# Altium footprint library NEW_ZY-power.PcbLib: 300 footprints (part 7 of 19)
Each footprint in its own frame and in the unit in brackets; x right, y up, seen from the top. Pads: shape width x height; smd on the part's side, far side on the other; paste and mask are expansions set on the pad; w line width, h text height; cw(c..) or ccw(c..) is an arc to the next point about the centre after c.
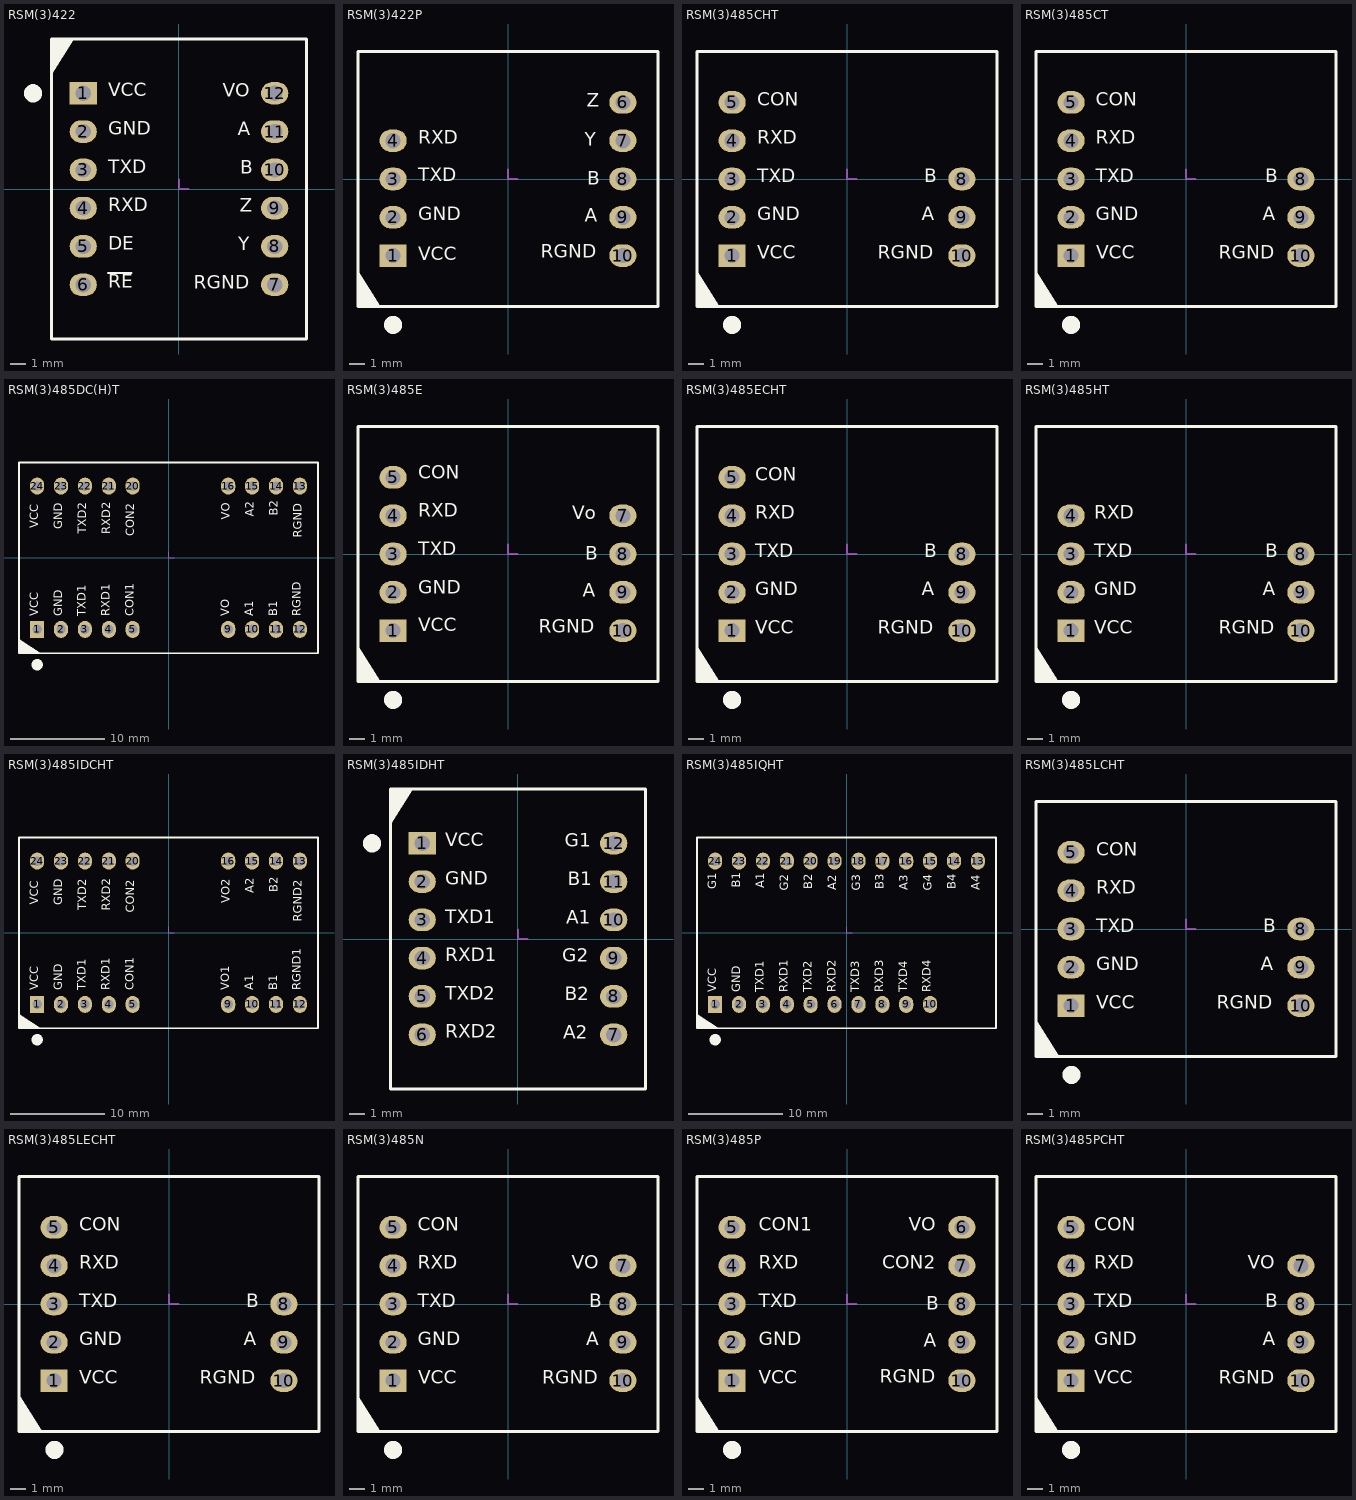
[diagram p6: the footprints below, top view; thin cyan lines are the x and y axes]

## RSM(3)422 [mm]
height 7.05
pads (12):
  rect 1.8x1.5 hole 1: 1(-6.35,6.35)
  oval 1.8x1.5 hole 1: 2(-6.35,3.81) 3(-6.35,1.27) 4(-6.35,-1.27) 5(-6.35,-3.81) 6(-6.35,-6.35) 7(6.35,-6.35) 8(6.35,-3.81) 9(6.35,-1.27) 10(6.35,1.27) 11(6.35,3.81) 12(6.35,6.35)
Top Overlay:
  circle w1: c-9.675,6.35 r0.1
  region: -8.45,7.62 -8.45,9.95 -6.99,9.95
  lines w0.152: -4.694,-5.575 -3.144,-5.575
  lines w0.2: -8.45,-9.95 -8.45,9.95 8.45,9.95 8.45,-9.95 -8.45,-9.95
  text "DE" at -4.7,-4.318 h1.52
  text "RE" at -4.7,-6.858 h1.52
  text "RGND" at 0.983,-6.909 h1.52
  text "Y" at 3.92,-4.364 h1.52
  text "RXD" at -4.7,-1.778 h1.52
  text "TXD" at -4.7,0.762 h1.52
  text "GND" at -4.7,3.302 h1.52
  text "VCC" at -4.699,5.842 h1.52
  text "A" at 3.903,3.272 h1.52
  text "B" at 4.076,0.726 h1.52
  text "Z" at 4.042,-1.819 h1.52
  text "VO" at 2.911,5.817 h1.52
Mechanical 15:
  lines w0.127: 0,0.635 0,0 0.635,0

## RSM(3)422P [mm]
height 7.05
pads (9):
  rect 1.8x1.5 hole 1: 1(-7.62,-5.08)
  oval 1.8x1.5 hole 1: 2(-7.62,-2.54) 3(-7.62,0) 4(-7.62,2.54) 6(7.62,5.08) 7(7.62,2.54) 8(7.62,0) 9(7.62,-2.54) 10(7.62,-5.08)
Top Overlay:
  circle w1: c-7.62,-9.675 r0.1
  region: -9.95,-6.12 -9.95,-8.45 -8.49,-8.45
  lines w0.2: -9.95,-8.45 -9.95,8.45 9.95,8.45 9.95,-8.45 -9.95,-8.45
  text "RGND" at 2.159,-5.537 h1.52
  text "A" at 5.079,-3.124 h1.52
  text "B" at 5.253,-0.686 h1.52
  text "Y" at 5.097,1.905 h1.52
  text "Z" at 5.218,4.496 h1.52
  text "RXD" at -5.969,2.032 h1.52
  text "TXD" at -5.969,-0.457 h1.52
  text "GND" at -5.969,-3.023 h1.52
  text "VCC" at -5.969,-5.69 h1.52
Mechanical 15:
  lines w0.127: 0,0.635 0,0 0.635,0

## RSM(3)485CHT [mm] "嵌入式隔离RS-485收发器"
height 7
pads (8):
  rect 1.8x1.5 hole 1: 1(-7.62,-5.08)
  oval 1.8x1.5 hole 1: 2(-7.62,-2.54) 3(-7.62,0) 4(-7.62,2.54) 5(-7.62,5.08) 8(7.62,0) 9(7.62,-2.54) 10(7.62,-5.08)
Top Overlay:
  circle w1: c-7.62,-9.675 r0.1
  region: -9.95,-6.12 -9.95,-8.45 -8.49,-8.45
  lines w0.2: -9.95,-8.45 9.95,-8.45 9.95,8.45 -9.95,8.45 -9.95,-8.45
  text "A" at 4.952,-3.048 h1.52
  text "B" at 5.126,-0.508 h1.52
  text "RGND" at 2.032,-5.588 h1.52
  text "TXD" at -5.969,-0.508 h1.52
  text "RXD" at -5.969,2.032 h1.52
  text "GND" at -5.969,-3.048 h1.52
  text "CON" at -5.969,4.572 h1.52
  text "VCC" at -5.969,-5.588 h1.52
Mechanical 15:
  lines w0.127: 0,0.635 0,0 0.635,0

## RSM(3)485CT [mm] "嵌入式隔离RS-485收发器"
height 7
pads (8):
  rect 1.8x1.5 hole 1: 1(-7.62,-5.08)
  oval 1.8x1.5 hole 1: 2(-7.62,-2.54) 3(-7.62,0) 4(-7.62,2.54) 5(-7.62,5.08) 8(7.62,0) 9(7.62,-2.54) 10(7.62,-5.08)
Top Overlay:
  circle w1: c-7.62,-9.675 r0.1
  region: -9.95,-6.12 -9.95,-8.45 -8.49,-8.45
  lines w0.2: -9.95,-8.45 9.95,-8.45 9.95,8.45 -9.95,8.45 -9.95,-8.45
  text "A" at 5.079,-3.048 h1.52
  text "B" at 5.253,-0.508 h1.52
  text "RGND" at 2.159,-5.588 h1.52
  text "TXD" at -5.97,-0.508 h1.52
  text "RXD" at -5.97,2.032 h1.52
  text "GND" at -5.97,-3.048 h1.52
  text "CON" at -5.97,4.572 h1.52
  text "VCC" at -5.969,-5.588 h1.52
Mechanical 15:
  lines w0.127: 0,0.635 0,0 0.635,0

## RSM(3)485DC(H)T [mm]
height 9.5
pads (18):
  rect 1.5x1.8 hole 1: 1(-13.97,-7.62)
  oval 1.5x1.8 hole 1: 2(-11.43,-7.62) 3(-8.89,-7.62) 4(-6.35,-7.62) 5(-3.81,-7.62) 9(6.35,-7.62) 10(8.89,-7.62) 11(11.43,-7.62) 12(13.97,-7.62) 13(13.97,7.62) 14(11.43,7.62) 15(8.89,7.62) 16(6.35,7.62) 20(-3.81,7.62) 21(-6.35,7.62) 22(-8.89,7.62) 23(-11.43,7.62) 24(-13.97,7.62)
Top Overlay:
  circle w1: c-13.97,-11.375 r0.1
  region: -13.57,-10.15 -15.9,-10.15 -15.9,-8.69
  lines w0.2: -15.9,-10.15 15.9,-10.15 15.9,10.15 -15.9,10.15 -15.9,-10.15
  text "VCC" at -13.538,-6.223 h1.52
  text "GND" at -10.998,-6.224 h1.52
  text "TXD1" at -8.458,-6.224 h1.52
  text "RXD1" at -5.918,-6.224 h1.52
  text "CON1" at -3.378,-6.224 h1.52
  text "VO" at 6.782,-6.223 h1.52
  text "A1" at 9.322,-6.224 h1.52
  text "B1" at 11.862,-6.224 h1.52
  text "RGND" at 14.402,-6.224 h1.52
  text "RGND" at 14.478,2.108 h1.52
  text "B2" at 11.931,4.443 h1.52
  text "A2" at 9.384,4.342 h1.52
  text "VO" at 6.837,4.037 h1.52
  text "VCC" at -13.538,3.122 h1.52
  text "GND" at -10.991,3.058 h1.52
  text "TXD2" at -8.444,2.56 h1.52
  text "CON2" at -3.35,2.294 h1.52
  text "RXD2" at -5.897,2.483 h1.52
Mechanical 15:
  lines w0.127: 0,0.635 0,0 0.635,0

## RSM(3)485E [mm]
height 7.05
pads (9):
  rect 1.8x1.5 hole 1: 1(-7.62,-5.08)
  oval 1.8x1.5 hole 1: 2(-7.62,-2.54) 3(-7.62,0) 4(-7.62,2.54) 5(-7.62,5.08) 7(7.62,2.54) 8(7.62,0) 9(7.62,-2.54) 10(7.62,-5.08)
Top Overlay:
  circle w1: c-7.62,-9.675 r0.1
  region: -9.95,-6.12 -9.95,-8.45 -8.49,-8.45
  lines w0.2: -9.95,-8.45 9.95,-8.45 9.95,8.45 -9.95,8.45 -9.95,-8.45
  text "VCC" at -5.969,-5.436 h1.52
  text "GND" at -5.969,-2.921 h1.52
  text "TXD" at -5.969,-0.381 h1.52
  text "RXD" at -5.969,2.159 h1.52
  text "CON" at -5.969,4.699 h1.52
  text "Vo" at 4.252,2.007 h1.52
  text "B" at 5.126,-0.686 h1.52
  text "A" at 4.952,-3.124 h1.52
  text "RGND" at 2.032,-5.537 h1.52
Mechanical 15:
  lines w0.127: 0,0.635 0,0 0.635,0

## RSM(3)485ECHT [mm]
height 7.05
pads (8):
  rect 1.8x1.5 hole 1: 1(-7.62,-5.08)
  oval 1.8x1.5 hole 1: 2(-7.62,-2.54) 3(-7.62,0) 4(-7.62,2.54) 5(-7.62,5.08) 8(7.62,0) 9(7.62,-2.54) 10(7.62,-5.08)
Top Overlay:
  circle w1: c-7.62,-9.675 r0.1
  region: -9.95,-6.12 -9.95,-8.45 -8.49,-8.45
  lines w0.2: -9.95,-8.45 9.95,-8.45 9.95,8.45 -9.95,8.45 -9.95,-8.45
  text "A" at 4.952,-3.048 h1.52
  text "B" at 5.126,-0.508 h1.52
  text "RGND" at 2.032,-5.588 h1.52
  text "TXD" at -6.097,-0.508 h1.52
  text "RXD" at -6.097,2.032 h1.52
  text "GND" at -6.097,-3.048 h1.52
  text "CON" at -6.097,4.572 h1.52
  text "VCC" at -6.096,-5.588 h1.52
Mechanical 15:
  lines w0.127: 0,0.635 0,0 0.635,0

## RSM(3)485HT [mm]
height 7.05
pads (7):
  rect 1.8x1.5 hole 1: 1(-7.62,-5.08)
  oval 1.8x1.5 hole 1: 2(-7.62,-2.54) 3(-7.62,0) 4(-7.62,2.54) 8(7.62,0) 9(7.62,-2.54) 10(7.62,-5.08)
Top Overlay:
  circle w1: c-7.62,-9.675 r0.1
  region: -9.95,-6.12 -9.95,-8.45 -8.49,-8.45
  lines w0.2: -9.95,-8.45 -9.95,8.45 9.95,8.45 9.95,-8.45 -9.95,-8.45
  text "VCC" at -6.096,-5.588 h1.52
  text "GND" at -6.097,-3.048 h1.52
  text "RXD" at -6.097,2.032 h1.52
  text "TXD" at -6.097,-0.508 h1.52
  text "RGND" at 2.159,-5.588 h1.52
  text "B" at 5.253,-0.508 h1.52
  text "A" at 5.079,-3.048 h1.52
Mechanical 15:
  lines w0.127: 0,0.635 0,0 0.635,0

## RSM(3)485IDCHT [mm]
height 6.5
pads (18):
  rect 1.5x1.8 hole 1: 1(-13.97,-7.62)
  oval 1.5x1.8 hole 1: 2(-11.43,-7.62) 3(-8.89,-7.62) 4(-6.35,-7.62) 5(-3.81,-7.62) 9(6.35,-7.62) 10(8.89,-7.62) 11(11.43,-7.62) 12(13.97,-7.62) 13(13.97,7.62) 14(11.43,7.62) 15(8.89,7.62) 16(6.35,7.62) 20(-3.81,7.62) 21(-6.35,7.62) 22(-8.89,7.62) 23(-11.43,7.62) 24(-13.97,7.62)
Top Overlay:
  circle w1: c-13.97,-11.375 r0.1
  region: -13.57,-10.15 -15.9,-10.15 -15.9,-8.69
  lines w0.2: -15.9,-10.15 -15.9,10.15 15.9,10.15 15.9,-10.15 -15.9,-10.15
  text "RXD2" at -5.897,2.328 h1.52
  text "CON2" at -3.35,2.139 h1.52
  text "TXD2" at -8.444,2.405 h1.52
  text "GND" at -10.991,2.903 h1.52
  text "VCC" at -13.538,2.966 h1.52
  text "VO2" at 6.837,3.134 h1.52
  text "A2" at 9.384,4.186 h1.52
  text "B2" at 11.931,4.287 h1.52
  text "RGND2" at 14.478,1.194 h1.52
  text "RGND1" at 14.402,-6.097 h1.52
  text "B1" at 11.862,-6.097 h1.52
  text "A1" at 9.322,-6.097 h1.52
  text "VO1" at 6.782,-6.096 h1.52
  text "CON1" at -3.378,-6.097 h1.52
  text "RXD1" at -5.918,-6.097 h1.52
  text "TXD1" at -8.458,-6.097 h1.52
  text "GND" at -10.998,-6.097 h1.52
  text "VCC" at -13.538,-6.096 h1.52
Mechanical 15:
  lines w0.127: 0,0.635 0,0 0.635,0

## RSM(3)485IDHT [mm]
height 7.05
pads (12):
  rect 1.8x1.5 hole 1: 1(-6.35,6.35)
  oval 1.8x1.5 hole 1: 2(-6.35,3.81) 3(-6.35,1.27) 4(-6.35,-1.27) 5(-6.35,-3.81) 6(-6.35,-6.35) 7(6.35,-6.35) 8(6.35,-3.81) 9(6.35,-1.27) 10(6.35,1.27) 11(6.35,3.81) 12(6.35,6.35)
Top Overlay:
  circle w1: c-9.675,6.35 r0.1
  region: -8.45,7.62 -8.45,9.95 -6.99,9.95
  lines w0.2: -8.45,-9.95 8.45,-9.95 8.45,9.95 -8.45,9.95 -8.45,-9.95
  text "G1" at 3.117,5.817 h1.52
  text "G2" at 2.939,-1.819 h1.52
  text "A1" at 3.193,0.726 h1.52
  text "B1" at 3.294,3.272 h1.52
  text "VCC" at -4.826,5.842 h1.52
  text "GND" at -4.827,3.302 h1.52
  text "TXD1" at -4.827,0.762 h1.52
  text "RXD1" at -4.827,-1.778 h1.52
  text "B2" at 3.115,-4.364 h1.52
  text "A2" at 3.014,-6.909 h1.52
  text "RXD2" at -4.827,-6.858 h1.52
  text "TXD2" at -4.827,-4.318 h1.52
Mechanical 15:
  lines w0.127: 0,0.635 0,0 0.635,0

## RSM(3)485IQHT [mm]
height 9.5
pads (22):
  rect 1.5x1.8 hole 1: 1(-13.97,-7.62)
  oval 1.5x1.8 hole 1: 2(-11.43,-7.62) 3(-8.89,-7.62) 4(-6.35,-7.62) 5(-3.81,-7.62) 6(-1.27,-7.62) 7(1.27,-7.62) 8(3.81,-7.62) 9(6.35,-7.62) 10(8.89,-7.62) 13(13.97,7.62) 14(11.43,7.62) 15(8.89,7.62) 16(6.35,7.62) 17(3.81,7.62) 18(1.27,7.62) 19(-1.27,7.62) 20(-3.81,7.62) 21(-6.35,7.62) 22(-8.89,7.62) 23(-11.43,7.62) 24(-13.97,7.62)
Top Overlay:
  circle w1: c-13.97,-11.375 r0.1
  region: -13.57,-10.15 -15.9,-10.15 -15.9,-8.69
  lines w0.2: -15.9,-10.15 -15.9,10.15 15.9,10.15 15.9,-10.15 -15.9,-10.15
  text "A2" at -0.79,4.53 h1.52
  text "G3" at 1.755,4.445 h1.52
  text "B3" at 4.3,4.622 h1.52
  text "RXD4" at 9.296,-6.326 h1.52
  text "TXD4" at 6.759,-6.326 h1.52
  text "RXD3" at 4.222,-6.326 h1.52
  text "TXD3" at 1.685,-6.326 h1.52
  text "RXD2" at -0.852,-6.326 h1.52
  text "G2" at -5.879,4.454 h1.52
  text "B2" at -3.334,4.631 h1.52
  text "A1" at -8.424,4.708 h1.52
  text "B1" at -10.968,4.809 h1.52
  text "G1" at -13.513,4.632 h1.52
  text "A3" at 6.844,4.521 h1.52
  text "G4" at 9.389,4.448 h1.52
  text "B4" at 11.933,4.625 h1.52
  text "A4" at 14.478,4.524 h1.52
  text "TXD2" at -3.389,-6.326 h1.52
  text "RXD1" at -5.927,-6.326 h1.52
  text "TXD1" at -8.464,-6.326 h1.52
  text "GND" at -11.001,-6.326 h1.52
  text "VCC" at -13.538,-6.325 h1.52
Mechanical 15:
  lines w0.127: 0,0.635 0,0 0.635,0

## RSM(3)485LCHT [mm]
height 7.1
pads (8):
  rect 1.8x1.5 hole 1: 1(-7.62,-5.08)
  oval 1.8x1.5 hole 1: 2(-7.62,-2.54) 3(-7.62,0) 4(-7.62,2.54) 5(-7.62,5.08) 8(7.62,0) 9(7.62,-2.54) 10(7.62,-5.08)
Top Overlay:
  circle w1: c-7.593,-9.675 r0.1
  region: -9.95,-6.223 -9.95,-8.45 -8.49,-8.45 -9.838,-6.298
  lines w0.15: -9.95,-6.12 -8.49,-8.45
  lines w0.2: -9.95,-8.45 -9.95,8.45 9.95,8.45 9.95,-8.45 -9.95,-8.45
  text "RGND" at 2.032,-5.588 h1.52
  text "A" at 4.952,-3.048 h1.52
  text "B" at 5.126,-0.508 h1.52
  text "CON" at -5.939,4.572 h1.52
  text "RXD" at -5.939,2.032 h1.52
  text "TXD" at -5.939,-0.508 h1.52
  text "VCC" at -5.938,-5.588 h1.52
  text "GND" at -5.939,-3.048 h1.52
Mechanical 15:
  lines w0.127: 0,0.635 0,0 0.635,0

## RSM(3)485LECHT [mm]
height 7.1
pads (8):
  rect 1.8x1.5 hole 1: 1(-7.62,-5.08)
  oval 1.8x1.5 hole 1: 2(-7.62,-2.54) 3(-7.62,0) 4(-7.62,2.54) 5(-7.62,5.08) 8(7.62,0) 9(7.62,-2.54) 10(7.62,-5.08)
Top Overlay:
  circle w1: c-7.593,-9.675 r0.1
  region: -9.95,-6.223 -9.95,-8.45 -8.49,-8.45 -9.838,-6.298
  lines w0.15: -9.95,-6.12 -8.49,-8.45
  lines w0.2: -9.95,-8.45 -9.95,8.45 9.95,8.45 9.95,-8.45 -9.95,-8.45
  text "RGND" at 2.032,-5.588 h1.52
  text "A" at 4.952,-3.048 h1.52
  text "B" at 5.126,-0.508 h1.52
  text "CON" at -5.939,4.572 h1.52
  text "RXD" at -5.939,2.032 h1.52
  text "TXD" at -5.939,-0.508 h1.52
  text "VCC" at -5.938,-5.588 h1.52
  text "GND" at -5.939,-3.048 h1.52
Mechanical 15:
  lines w0.127: 0,0.635 0,0 0.635,0

## RSM(3)485N [mm]
height 7.05
pads (9):
  rect 1.8x1.5 hole 1: 1(-7.62,-5.08)
  oval 1.8x1.5 hole 1: 2(-7.62,-2.54) 3(-7.62,0) 4(-7.62,2.54) 5(-7.62,5.08) 7(7.62,2.54) 8(7.62,0) 9(7.62,-2.54) 10(7.62,-5.08)
Top Overlay:
  circle w1: c-7.62,-9.675 r0.1
  region: -9.95,-6.12 -9.95,-8.45 -8.49,-8.45
  lines w0.2: -9.95,-8.45 -9.95,8.45 9.95,8.45 9.95,-8.45 -9.95,-8.45
  text "VO" at 4.215,2.032 h1.52
  text "VCC" at -5.969,-5.588 h1.52
  text "CON" at -5.97,4.572 h1.52
  text "GND" at -5.97,-3.048 h1.52
  text "RXD" at -5.97,2.032 h1.52
  text "TXD" at -5.97,-0.508 h1.52
  text "RGND" at 2.286,-5.588 h1.52
  text "B" at 5.38,-0.508 h1.52
  text "A" at 5.206,-3.048 h1.52
Mechanical 15:
  lines w0.127: 0,0.635 0,0 0.635,0

## RSM(3)485P [mm]
height 7.05
pads (10):
  rect 1.8x1.5 hole 1: 1(-7.62,-5.08)
  oval 1.8x1.5 hole 1: 2(-7.62,-2.54) 3(-7.62,0) 4(-7.62,2.54) 5(-7.62,5.08) 6(7.62,5.08) 7(7.62,2.54) 8(7.62,0) 9(7.62,-2.54) 10(7.62,-5.08)
Top Overlay:
  circle w1: c-7.62,-9.675 r0.1
  region: -9.95,-6.12 -9.95,-8.45 -8.49,-8.45
  lines w0.2: -9.95,-8.45 -9.95,8.45 9.95,8.45 9.95,-8.45 -9.95,-8.45
  text "RGND" at 2.159,-5.537 h1.52
  text "A" at 5.079,-3.124 h1.52
  text "B" at 5.253,-0.686 h1.52
  text "CON1" at -5.843,4.572 h1.52
  text "RXD" at -5.843,2.032 h1.52
  text "TXD" at -5.843,-0.508 h1.52
  text "GND" at -5.843,-3.023 h1.52
  text "VCC" at -5.842,-5.588 h1.52
  text "CON2" at 2.345,2.032 h1.52
  text "VO" at 4.088,4.572 h1.52
Mechanical 15:
  lines w0.127: 0,0.635 0,0 0.635,0

## RSM(3)485PCHT [mm]
height 7.05
pads (9):
  rect 1.8x1.5 hole 1: 1(-7.62,-5.08)
  oval 1.8x1.5 hole 1: 2(-7.62,-2.54) 3(-7.62,0) 4(-7.62,2.54) 5(-7.62,5.08) 7(7.62,2.54) 8(7.62,0) 9(7.62,-2.54) 10(7.62,-5.08)
Top Overlay:
  circle w1: c-7.62,-9.675 r0.1
  region: -9.95,-6.12 -9.95,-8.45 -8.49,-8.45
  lines w0.2: -9.95,-8.45 9.95,-8.45 9.95,8.45 -9.95,8.45 -9.95,-8.45
  text "VO" at 4.088,2.032 h1.52
  text "VCC" at -6.096,-5.588 h1.52
  text "CON" at -6.097,4.572 h1.52
  text "GND" at -6.097,-3.048 h1.52
  text "RXD" at -6.097,2.032 h1.52
  text "TXD" at -6.097,-0.508 h1.52
  text "RGND" at 2.159,-5.588 h1.52
  text "B" at 5.253,-0.508 h1.52
  text "A" at 5.079,-3.048 h1.52
Mechanical 15:
  lines w0.127: 0,0.635 0,0 0.635,0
